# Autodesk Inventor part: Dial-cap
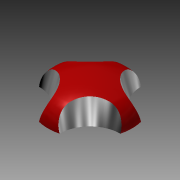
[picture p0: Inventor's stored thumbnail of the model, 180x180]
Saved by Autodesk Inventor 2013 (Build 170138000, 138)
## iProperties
Shininess: 64.0
Length Units: 11272
Angle Units: 11279
Time Units: 11290
Mass Units: 11286
Length Display Precision: 3
Angle Display Precision: 2
Compacted: True
Created: 2001-11
Part Number: Dial-cap
Document SubType Name: Modeling
Designer: Autodesk, Inc.
Mass: 1.44224 g
Surface Area: 10.3588 cm^2
Volume: 1.44224 cm^3
Density: 1 g/cm^3
Material: Generic
Density: 0.0
Volumn: 0.0
Area: 0.0
PropertySet Name: Model Information
Control State: 0
Master: False
Checked Out: False
Author: Autodesk, Inc.
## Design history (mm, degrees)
sketch "Sketch1"
  geometry: L1 (133.744, 47.494)-(133.744, 91.062); L2 (145.889, 43.525)-(145.889, 43.609); L3 (138.904, 43.525)-(145.889, 43.525); L4 (138.904, 44.319)-(138.904, 43.525); L5 (136.7, 44.319)-(138.904, 44.319); L6 (136.7, 47.494)-(136.7, 44.319); L7 (133.744, 47.494)-(136.7, 47.494); L8 (133.744, 54.846)-(133.744, 91.062); A1 r 23.812 centre (133.744, 26.857) between (141.999, 49.192) and (133.744, 50.669); A2 r 5.953 centre (139.936, 43.609) between (145.889, 43.609) and (141.999, 49.192)
  constraints: 16 end point, 4 point on circle, 4 vertical, 3 horizontal, 2 centre point, 2 point on line, 1 tangent, 1 other
revolve "RevolutionFull1" sketch "Sketch1" stored, may be unused: angle "d0" = 360 deg
sketch "Sketch3"
  geometry: A1 r 12.144 centre (0, 0) between (-2.977, -11.774) and (-11.774, -2.977) reference; A2 r 8.797 centre (-11.774, -11.774) between (-2.977, -11.774) and (-11.774, -2.977)
  constraints: 4 point on circle, 1 centre point
extrude "ExtrusionThru1" cut sketch "Sketch3" stored distance "d3" = 3.302; taper "d4" = 15 deg
pattern_circular "PolarArray1" dims angle "d7" = 360 deg
sketch "Sketch5"
  geometry: L1 (-2.887, 1.667)-(-2.887, -1.667); L2 (0, 3.334)-(-2.887, 1.667); L3 (2.887, 1.667)-(0, 3.334); L4 (2.887, -1.667)-(2.887, 1.667); L5 (0, -3.334)-(2.887, -1.667); L6 (-2.887, -1.667)-(0, -3.334)
  constraints: 12 end point, 2 parallel, 2 vertical
extrude "ExtrusionToPlane1" cut sketch "Sketch5" stored distance "d8" = 3.302; taper "d9" = 0 deg
body "Solid1"
other parameters: "d1" = 0, "d2" = 0
